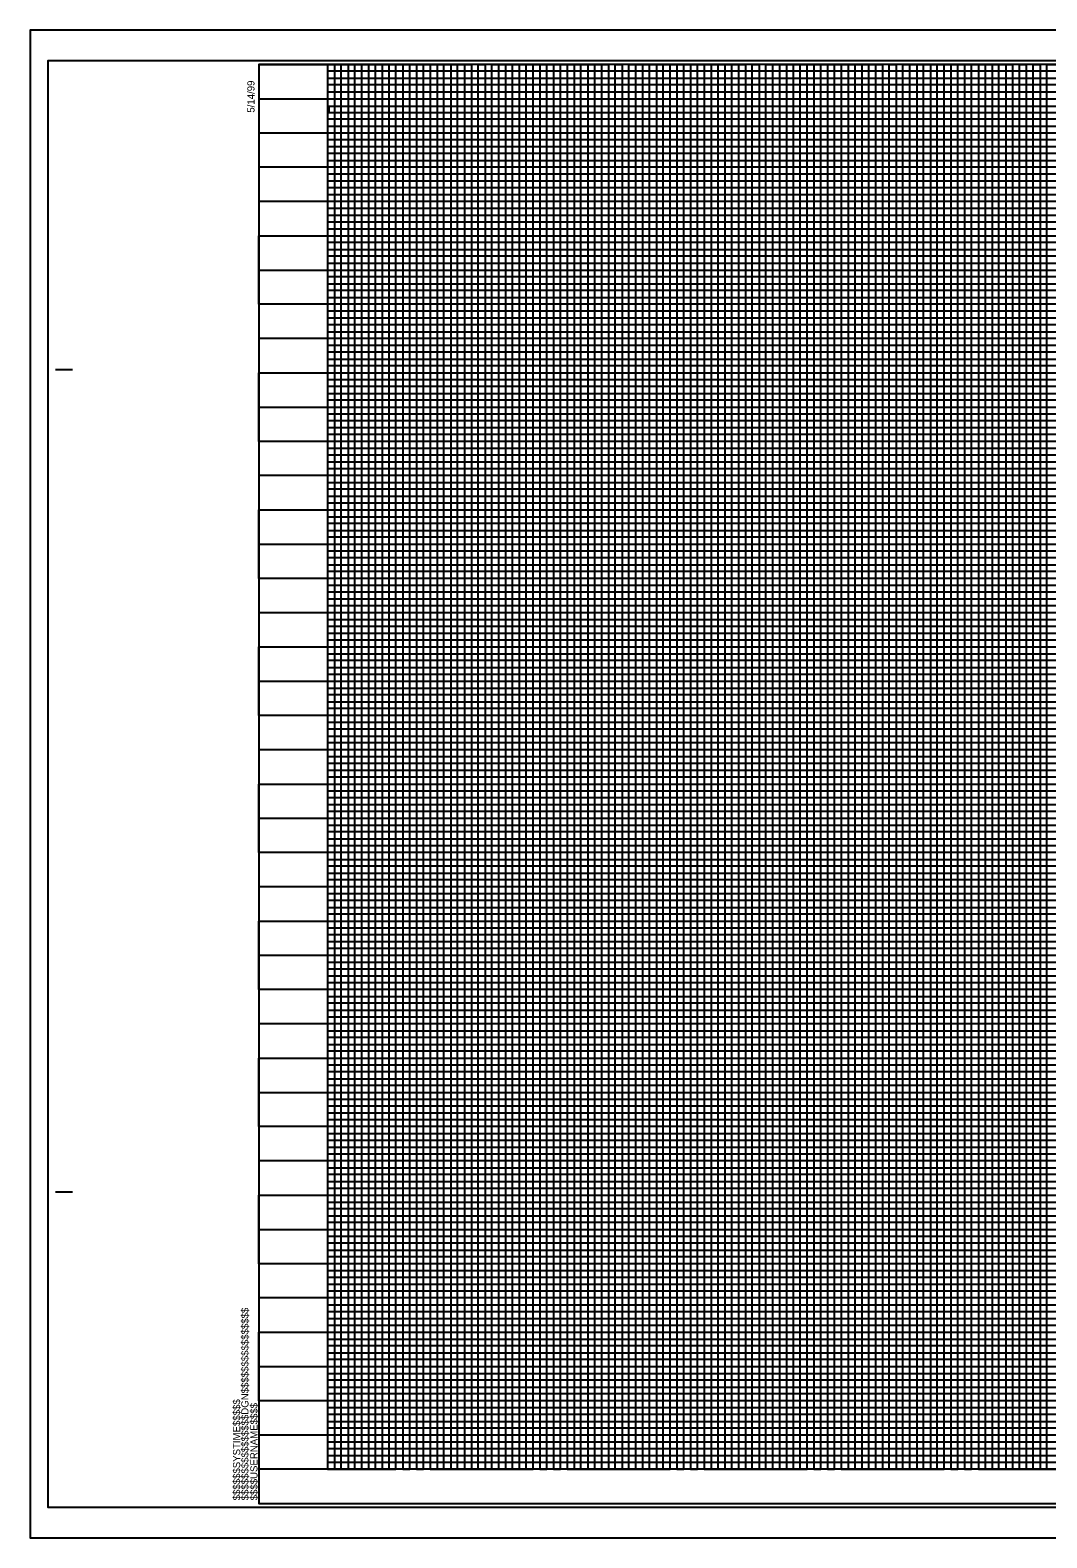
# Model space of a CAD drawing. Extents: x 2345490 to 2436403, y 465165 to 573888.
# Drawn here: x 2381550 to 2382292, y 544859 to 545959 of the extents above; entities that cross this region are included whole.
import ezdxf

# ---------------------------------------------------------------- set-up
doc = ezdxf.new("R2010")
doc.units = 0
for name, color, linetype in [('Old_Level_18', 7, 'Continuous'), ('Old_Level_40', 7, 'Continuous'), ('Old_Level_41', 7, 'Continuous'), ('Old_Level_42', 7, 'Continuous'), ('Old_Level_43', 7, 'Continuous'), ('Old_Level_50', 7, 'Continuous'), ('Old_Level_51', 7, 'Continuous'), ('Old_Level_52', 7, 'Continuous')]:
    doc.layers.add(name, color=color, linetype=linetype)

msp = doc.modelspace()

# ---------------------------------------------------------------- linework, layer by layer
at = {"layer": 'Old_Level_18'}
msp.add_line((2381716.79875, 544884.17225), (2381716.79875, 544884.17225), dxfattribs=at)
msp.add_line((2381716.79875, 544884.17225), (2381716.79875, 544884.17225), dxfattribs=at)
msp.add_lwpolyline([(2383216.79875, 545934.17225), (2381716.79875, 545934.17225), (2381716.79875, 544884.17225), (2383216.79875, 544884.17225)], close=True, dxfattribs=at)
at = {"layer": 'Old_Level_40'}
msp.add_line((2381716.79875, 544884.17225), (2381716.79875, 544884.17225), dxfattribs=at)
msp.add_line((2381716.79875, 544884.17225), (2381716.79875, 544884.17225), dxfattribs=at)
msp.add_line((2381716.79875, 544884.17225), (2381716.79875, 544884.17225), dxfattribs=at)
msp.add_line((2381716.79875, 544884.17225), (2381716.79875, 544884.17225), dxfattribs=at)
at = {"layer": 'Old_Level_41'}
for p, q in [((2381568.29875, 545711.67225), (2381580.79875, 545711.67225)), ((2381568.29875, 545111.67225), (2381580.79875, 545111.67225)), ((2383216.79875, 544909.17225), (2381716.79875, 544909.17225))]:
    msp.add_line(p, q, dxfattribs=at)
for points in [[(2381716.79875, 545934.17225), (2381766.79875, 545934.17225), (2381766.79875, 544909.17225), (2381816.79875, 544909.17225), (2381816.79875, 545934.17225), (2381866.79875, 545934.17225), (2381866.79875, 544909.17225), (2381916.79875, 544909.17225), (2381916.79875, 545934.17225), (2381966.79875, 545934.17225), (2381966.79875, 544909.17225), (2382016.79875, 544909.17225), (2382016.79875, 545934.17225), (2382066.79875, 545934.17225), (2382066.79875, 544909.17225), (2382116.79875, 544909.17225), (2382116.79875, 545934.17225), (2382166.79875, 545934.17225), (2382166.79875, 544909.17225), (2382216.79875, 544909.17225), (2382216.79875, 545934.17225), (2382266.79875, 545934.17225), (2382266.79875, 544909.17225), (2382316.79875, 544909.17225)], [(2381791.79875, 544909.17225), (2381791.79875, 545934.17225), (2381841.79875, 545934.17225), (2381841.79875, 544909.17225), (2381891.79875, 544909.17225), (2381891.79875, 545934.17225), (2381941.79875, 545934.17225), (2381941.79875, 544909.17225), (2381991.79875, 544909.17225), (2381991.79875, 545934.17225), (2382041.79875, 545934.17225), (2382041.79875, 544909.17225), (2382091.79875, 544909.17225), (2382091.79875, 545934.17225), (2382141.79875, 545934.17225), (2382141.79875, 544909.17225), (2382191.79875, 544909.17225), (2382191.79875, 545934.17225), (2382241.79875, 545934.17225), (2382241.79875, 544909.17225), (2382291.79875, 544909.17225), (2382291.79875, 545934.17225), (2382341.79875, 545934.17225)], [(2381716.79875, 545884.17225), (2383016.74875, 545884.17225)], [(2383016.74875, 545834.17225), (2381716.79875, 545834.17225), (2381716.79875, 545784.12225), (2383216.79875, 545784.12225)], [(2383216.79875, 545759.17225), (2381716.79875, 545759.17225), (2381716.79875, 545809.17225), (2383016.74875, 545809.17225)], [(2383216.79875, 545734.17225), (2381716.79875, 545734.17225), (2381716.79875, 545684.17225), (2383216.79875, 545684.17225)], [(2383216.79875, 545659.17225), (2381716.79875, 545659.17225), (2381716.79875, 545709.17225), (2383216.79875, 545709.17225)], [(2383216.79875, 545634.17225), (2381716.79875, 545634.17225), (2381716.79875, 545584.17225), (2383216.79875, 545584.17225)], [(2383216.79875, 545534.17225), (2381716.79875, 545534.17225), (2381716.79875, 545484.17225), (2383216.79875, 545484.17225)], [(2383216.79875, 545434.17225), (2381716.79875, 545434.17225), (2381716.79875, 545384.17225), (2383216.79875, 545384.17225)], [(2383216.79875, 545334.17225), (2381716.79875, 545334.17225), (2381716.79875, 545284.17225), (2383216.79875, 545284.17225)], [(2383216.79875, 545259.17225), (2381716.79875, 545259.17225), (2381716.79875, 545309.17225), (2383216.79875, 545309.17225)], [(2383216.79875, 545234.17225), (2381716.79875, 545234.17225), (2381716.79875, 545184.17225), (2383216.79875, 545184.17225)], [(2383216.79875, 545159.17225), (2381716.79875, 545159.17225), (2381716.79875, 545209.17225), (2383216.79875, 545209.17225)], [(2383216.79875, 545134.17225), (2381716.79875, 545134.17225), (2381716.79875, 545084.17225), (2383216.79875, 545084.17225)], [(2383216.79875, 545034.17225), (2381716.79875, 545034.17225), (2381716.79875, 544984.17225), (2383216.79875, 544984.17225)], [(2383216.79875, 544959.17225), (2381716.79875, 544959.17225), (2381716.79875, 545009.17225), (2383216.79875, 545009.17225)], [(2383216.79875, 544934.17225), (2381716.79875, 544934.17225)], [(2381754.29875, 544884.17225), (2381754.29875, 544884.17225)]]:
    msp.add_lwpolyline(points, dxfattribs=at)
at = {"layer": 'Old_Level_42'}
for points in [[(2383016.74875, 545859.17225), (2381716.89875, 545859.17225), (2381716.89875, 545909.12225), (2383016.74875, 545909.12225)], [(2383216.79875, 545559.17225), (2381716.79875, 545559.17225), (2381716.79875, 545609.17225), (2383216.79875, 545609.17225)], [(2383216.79875, 545459.17225), (2381716.79875, 545459.17225), (2381716.79875, 545509.17225), (2383216.79875, 545509.17225)], [(2383216.79875, 545359.17225), (2381716.79875, 545359.17225), (2381716.79875, 545409.17225), (2383216.79875, 545409.17225)], [(2383216.79875, 545059.17225), (2381716.79875, 545059.17225), (2381716.79875, 545109.17225), (2383216.79875, 545109.17225)]]:
    msp.add_lwpolyline(points, dxfattribs=at)
at = {"layer": 'Old_Level_43'}
for p, q in [((2383166.79875, 545754.17225), (2381766.79875, 545754.17225)), ((2381766.79875, 545754.17225), (2381766.79875, 545749.17225)), ((2381766.79875, 545749.17225), (2383166.79875, 545749.17225)), ((2383166.79875, 545729.17225), (2381766.79875, 545729.17225))]:
    msp.add_line(p, q, dxfattribs=at)
for points in [[(2381771.79875, 545934.17225), (2381776.79875, 545934.17225), (2381781.79875, 545934.17225), (2381786.79875, 545934.17225), (2381796.79875, 545934.17225), (2381763.74875, 545934.17225), (2381768.74875, 545934.17225), (2381726.79875, 545934.17225), (2381731.79875, 545934.17225), (2381736.79875, 545934.17225), (2381746.79875, 545934.17225), (2381751.79875, 545934.17225), (2381756.79875, 545934.17225), (2381761.79875, 545934.17225), (2381771.79875, 545934.17225), (2381771.79875, 544909.17225), (2381776.79875, 544909.17225), (2381776.79875, 545934.17225), (2381781.79875, 545934.17225), (2381781.79875, 544909.17225), (2381786.79875, 544909.17225), (2381786.79875, 545934.17225), (2381796.79875, 545934.17225), (2381796.79875, 544909.17225), (2381801.79875, 544909.17225), (2381801.79875, 545934.17225), (2381806.79875, 545934.17225), (2381806.79875, 544909.17225), (2381811.79875, 544909.17225), (2381811.79875, 545934.17225), (2381821.79875, 545934.17225), (2381821.79875, 544909.17225), (2381826.79875, 544909.17225), (2381826.79875, 545934.17225), (2381831.79875, 545934.17225), (2381831.79875, 544909.17225), (2381836.79875, 544909.17225), (2381836.79875, 545934.17225), (2381846.79875, 545934.17225), (2381846.79875, 544909.17225), (2381851.79875, 544909.17225), (2381851.79875, 545934.17225), (2381856.79875, 545934.17225), (2381856.79875, 544909.17225), (2381861.79875, 544909.17225), (2381861.79875, 545934.17225), (2381871.79875, 545934.17225), (2381871.79875, 544909.17225), (2381876.79875, 544909.17225), (2381876.79875, 545934.17225), (2381881.79875, 545934.17225), (2381881.79875, 544909.17225), (2381886.79875, 544909.17225), (2381886.79875, 545934.17225), (2381896.79875, 545934.17225), (2381896.79875, 544909.17225), (2381901.79875, 544909.17225), (2381901.79875, 545934.17225), (2381906.79875, 545934.17225), (2381906.79875, 544909.17225), (2381911.79875, 544909.17225), (2381911.79875, 545934.17225), (2381921.79875, 545934.17225), (2381921.79875, 544909.17225), (2381926.79875, 544909.17225), (2381926.79875, 545934.17225), (2381931.79875, 545934.17225), (2381931.79875, 544909.17225)], [(2381931.79875, 544909.17225), (2381936.79875, 544909.17225), (2381936.79875, 545934.17225), (2381946.79875, 545934.17225), (2381946.79875, 544909.17225), (2381951.79875, 544909.17225), (2381951.79875, 545934.17225), (2381956.79875, 545934.17225), (2381956.79875, 544909.17225), (2381961.79875, 544909.17225), (2381961.79875, 545934.17225), (2381971.79875, 545934.17225), (2381971.79875, 544909.17225), (2381976.79875, 544909.17225), (2381976.79875, 545934.17225), (2381976.79875, 545934.17225), (2381981.79875, 545934.17225), (2381981.79875, 544909.17225), (2381986.79875, 544909.17225), (2381986.79875, 545934.17225), (2381996.79875, 545934.17225), (2381996.79875, 544909.17225), (2382001.79875, 544909.17225), (2382001.79875, 545934.17225), (2382006.79875, 545934.17225), (2382006.79875, 544909.17225), (2382011.79875, 544909.17225), (2382011.79875, 545934.17225), (2382021.79875, 545934.17225), (2382021.79875, 544909.17225), (2382026.79875, 544909.17225), (2382026.79875, 545934.17225), (2382031.79875, 545934.17225), (2382031.79875, 544909.17225), (2382036.79875, 544909.17225), (2382036.79875, 545934.17225), (2382046.79875, 545934.17225), (2382046.79875, 544909.17225), (2382051.79875, 544909.17225), (2382051.79875, 545934.17225), (2382056.79875, 545934.17225), (2382056.79875, 544909.17225), (2382061.79875, 544909.17225), (2382061.79875, 545934.17225), (2382071.79875, 545934.17225), (2382071.79875, 544909.17225), (2382076.79875, 544909.17225), (2382076.79875, 545934.17225), (2382081.79875, 545934.17225), (2382081.79875, 544909.17225), (2382086.79875, 544909.17225), (2382086.79875, 545934.17225), (2382096.79875, 545934.17225), (2382096.79875, 544909.17225), (2382111.79875, 544909.17225), (2382111.79875, 545934.17225), (2382121.79875, 545934.17225), (2382121.79875, 544909.17225), (2382126.79875, 544909.17225), (2382126.79875, 545934.17225), (2382131.79875, 545934.17225), (2382131.79875, 544909.17225), (2382136.79875, 544909.17225), (2382136.79875, 545934.17225), (2382146.79875, 545934.17225), (2382146.79875, 544909.17225), (2382151.79875, 544909.17225), (2382151.79875, 545934.17225), (2382156.79875, 545934.17225), (2382156.79875, 544909.17225), (2382161.79875, 544909.17225), (2382161.79875, 545934.17225), (2382171.79875, 545934.17225), (2382171.79875, 544909.17225), (2382176.79875, 544909.17225), (2382176.79875, 545934.17225), (2382181.79875, 545934.17225), (2382181.79875, 544909.17225), (2382186.79875, 544909.17225), (2382186.79875, 545934.17225), (2382196.79875, 545934.17225), (2382196.79875, 544909.17225), (2382201.79875, 544909.17225), (2382201.79875, 545934.17225), (2382206.79875, 545934.17225), (2382206.79875, 544909.17225), (2382211.79875, 544909.17225), (2382211.79875, 545934.17225), (2382221.79875, 545934.17225), (2382221.79875, 544909.17225), (2382226.79875, 544909.17225), (2382226.79875, 545934.17225), (2382231.79875, 545934.17225), (2382231.79875, 544909.17225), (2382236.79875, 544909.17225), (2382236.79875, 545934.17225), (2382246.79875, 545934.17225), (2382246.79875, 544909.17225)], [(2382101.79875, 545934.17225), (2382101.79875, 544909.17225), (2382106.79875, 544909.17225), (2382106.79875, 545934.17225)], [(2382101.79875, 545933.57225), (2382101.79875, 544909.17225), (2382106.79875, 544909.17225), (2382106.79875, 545933.57225)], [(2382251.79875, 545934.17225), (2382251.79875, 544909.17225), (2382256.79875, 544909.17225), (2382256.79875, 545934.17225), (2382261.79875, 545934.17225), (2382261.79875, 544909.17225), (2382271.79875, 544909.17225), (2382271.79875, 545934.17225), (2382276.79875, 545934.17225), (2382276.79875, 544909.17225), (2382281.79875, 544909.17225), (2382281.79875, 545934.17225), (2382286.79875, 545934.17225), (2382286.79875, 544909.17225)], [(2383016.74875, 545929.17225), (2381766.79875, 545929.17225), (2381766.79875, 545924.17225), (2383016.74875, 545924.17225)], [(2383016.74875, 545919.17225), (2381766.79875, 545919.17225), (2381766.79875, 545914.17225), (2383016.74875, 545914.17225)], [(2383016.74875, 545903.42225), (2381767.79875, 545903.42225), (2381767.79875, 545899.17225), (2383016.74875, 545899.17225)], [(2383016.74875, 545894.17225), (2381766.79875, 545894.17225), (2381766.79875, 545889.17225), (2383016.74875, 545889.17225)], [(2383016.74875, 545879.17225), (2381766.79875, 545879.17225), (2381766.79875, 545874.17225), (2383016.74875, 545874.17225)], [(2383016.74875, 545869.17225), (2381766.79875, 545869.17225), (2381766.79875, 545864.17225), (2383016.74875, 545864.17225)], [(2383016.74875, 545854.17225), (2381766.79875, 545854.17225), (2381766.79875, 545849.17225), (2383016.74875, 545849.17225)], [(2383016.74875, 545844.17225), (2381766.79875, 545844.17225), (2381766.79875, 545839.17225), (2383016.74875, 545839.17225)], [(2383016.74875, 545829.17225), (2381766.79875, 545829.17225), (2381766.79875, 545824.17225), (2383016.74875, 545824.17225)], [(2383016.74875, 545819.17225), (2381766.79875, 545819.17225), (2381766.79875, 545814.17225), (2383016.74875, 545814.17225)], [(2383016.74875, 545804.17225), (2381766.79875, 545804.17225), (2381766.79875, 545799.17225), (2383016.74875, 545799.17225)], [(2383166.79875, 545794.17225), (2381766.79875, 545794.17225), (2381766.79875, 545794.17225), (2381766.79875, 545774.17225), (2383166.79875, 545774.17225)], [(2381766.79875, 545789.17225), (2383166.79875, 545789.17225)], [(2383166.79875, 545779.17225), (2381766.79875, 545779.17225)], [(2383166.79875, 545769.17225), (2381766.79875, 545769.17225), (2381766.79875, 545764.17225), (2383166.79875, 545764.17225)], [(2383166.79875, 545744.17225), (2381766.79875, 545744.17225), (2381766.79875, 545739.17225), (2383166.79875, 545739.17225)], [(2383166.79875, 545724.17225), (2381766.79875, 545724.17225), (2381766.79875, 545719.17225), (2383166.79875, 545719.17225)], [(2383166.79875, 545714.17225), (2381766.79875, 545714.17225)], [(2381766.79875, 545704.17225), (2383166.79875, 545704.17225)], [(2383166.79875, 545699.17225), (2381766.79875, 545699.17225), (2381766.79875, 545694.17225), (2383166.79875, 545694.17225)], [(2383166.79875, 545689.17225), (2381766.79875, 545689.17225), (2381766.79875, 545679.17225), (2383166.79875, 545679.17225)], [(2383166.79875, 545674.17225), (2381766.79875, 545674.17225), (2381766.79875, 545669.17225), (2383166.79875, 545669.17225)], [(2383166.79875, 545664.17225), (2381766.79875, 545664.17225), (2381766.79875, 545654.17225), (2383166.79875, 545654.17225)], [(2383166.79875, 545649.17225), (2381766.79875, 545649.17225), (2381766.79875, 545644.17225), (2383166.79875, 545644.17225)], [(2383166.79875, 545639.17225), (2381766.79875, 545639.17225), (2381766.79875, 545629.17225), (2383166.79875, 545629.17225)], [(2383166.79875, 545624.17225), (2381766.79875, 545624.17225), (2381766.79875, 545619.17225), (2383166.79875, 545619.17225)], [(2383166.79875, 545614.17225), (2381766.79875, 545614.17225), (2381766.79875, 545604.17225), (2383166.79875, 545604.17225)], [(2383166.79875, 545599.17225), (2381766.79875, 545599.17225), (2381766.79875, 545594.17225), (2383166.79875, 545594.17225)], [(2383166.79875, 545589.17225), (2381766.79875, 545589.17225), (2381766.79875, 545579.17225), (2383166.79875, 545579.17225)], [(2383166.79875, 545574.17225), (2381766.79875, 545574.17225), (2381766.79875, 545569.17225), (2383166.79875, 545569.17225)], [(2383166.79875, 545564.17225), (2381766.79875, 545564.17225), (2381766.79875, 545554.17225), (2383166.79875, 545554.17225)], [(2383166.79875, 545549.17225), (2381766.79875, 545549.17225), (2381766.79875, 545544.17225), (2383166.79875, 545544.17225)], [(2383166.79875, 545539.17225), (2381766.79875, 545539.17225), (2381766.79875, 545529.17225), (2383166.79875, 545529.17225)], [(2383166.79875, 545524.17225), (2381766.79875, 545524.17225), (2381766.79875, 545519.17225), (2383166.79875, 545519.17225)], [(2383166.79875, 545514.17225), (2381766.79875, 545514.17225), (2381766.79875, 545504.17225), (2383166.79875, 545504.17225)], [(2383166.79875, 545499.17225), (2381766.79875, 545499.17225), (2381766.79875, 545494.17225), (2383166.79875, 545494.17225)], [(2383166.79875, 545489.17225), (2381766.79875, 545489.17225), (2381766.79875, 545479.17225), (2383166.79875, 545479.17225)], [(2383166.79875, 545474.17225), (2381766.79875, 545474.17225), (2381766.79875, 545469.17225), (2383166.79875, 545469.17225)], [(2383166.79875, 545464.17225), (2381766.79875, 545464.17225), (2381766.79875, 545454.17225), (2383166.79875, 545454.17225)], [(2383166.79875, 545449.17225), (2381766.79875, 545449.17225), (2381766.79875, 545444.17225), (2383166.79875, 545444.17225)], [(2383166.79875, 545439.17225), (2381766.79875, 545439.17225), (2381766.79875, 545429.17225), (2383166.79875, 545429.17225)], [(2383166.79875, 545424.17225), (2381766.79875, 545424.17225), (2381766.79875, 545419.17225), (2383166.79875, 545419.17225)], [(2383166.79875, 545414.17225), (2381766.79875, 545414.17225)], [(2381766.79875, 545404.17225), (2383166.79875, 545404.17225)], [(2383166.79875, 545399.17225), (2381766.79875, 545399.17225), (2381766.79875, 545394.17225), (2383166.79875, 545394.17225)], [(2383166.79875, 545389.17225), (2381766.79875, 545389.17225), (2381766.79875, 545379.17225), (2383166.79875, 545379.17225)], [(2383166.79875, 545374.17225), (2381766.79875, 545374.17225), (2381766.79875, 545369.17225), (2383166.79875, 545369.17225)], [(2383166.79875, 545364.17225), (2381766.79875, 545364.17225), (2381766.79875, 545354.17225), (2383166.79875, 545354.17225)], [(2383166.79875, 545349.17225), (2381766.79875, 545349.17225), (2381766.79875, 545344.17225), (2383166.79875, 545344.17225)], [(2383166.79875, 545339.17225), (2381766.79875, 545339.17225), (2381766.79875, 545329.17225), (2383166.79875, 545329.17225)], [(2383166.79875, 545324.17225), (2381766.79875, 545324.17225), (2381766.79875, 545319.17225), (2383166.79875, 545319.17225)], [(2383166.79875, 545314.17225), (2381766.79875, 545314.17225), (2381766.79875, 545304.17225), (2383166.79875, 545304.17225)], [(2383166.79875, 545299.17225), (2381766.79875, 545299.17225), (2381766.79875, 545294.17225), (2383166.79875, 545294.17225)], [(2383166.79875, 545289.17225), (2381766.79875, 545289.17225), (2381766.79875, 545279.17225), (2383166.79875, 545279.17225)], [(2383166.79875, 545274.17225), (2381766.79875, 545274.17225), (2381766.79875, 545269.17225), (2383166.79875, 545269.17225)], [(2383166.79875, 545264.17225), (2381766.79875, 545264.17225), (2381766.79875, 545254.17225), (2383166.79875, 545254.17225)], [(2383166.79875, 545249.17225), (2381766.79875, 545249.17225), (2381766.79875, 545244.17225), (2383166.79875, 545244.17225)], [(2383166.79875, 545239.17225), (2381766.79875, 545239.17225), (2381766.79875, 545229.17225), (2383166.79875, 545229.17225)], [(2383166.79875, 545224.17225), (2381766.79875, 545224.17225), (2381766.79875, 545219.17225), (2383166.79875, 545219.17225)], [(2383166.79875, 545214.17225), (2381766.79875, 545214.17225), (2381766.79875, 545204.17225), (2383166.79875, 545204.17225)], [(2383166.79875, 545199.17225), (2381766.79875, 545199.17225), (2381766.79875, 545194.17225), (2383166.79875, 545194.17225)], [(2383166.79875, 545189.17225), (2381766.79875, 545189.17225), (2381766.79875, 545179.17225), (2383166.79875, 545179.17225)], [(2383166.79875, 545174.17225), (2381766.79875, 545174.17225), (2381766.79875, 545169.17225), (2383166.79875, 545169.17225)], [(2383166.79875, 545164.17225), (2381766.79875, 545164.17225), (2381766.79875, 545154.17225), (2383166.79875, 545154.17225)], [(2383166.79875, 545149.17225), (2381766.79875, 545149.17225), (2381766.79875, 545144.17225), (2383166.79875, 545144.17225)], [(2383166.79875, 545139.17225), (2381766.79875, 545139.17225), (2381766.79875, 545129.17225), (2383166.79875, 545129.17225)], [(2383166.79875, 545124.17225), (2381766.79875, 545124.17225), (2381766.79875, 545119.17225), (2383166.79875, 545119.17225)], [(2383166.79875, 545114.17225), (2381766.79875, 545114.17225)], [(2381766.79875, 545104.17225), (2383166.79875, 545104.17225)], [(2383166.79875, 545099.17225), (2381766.79875, 545099.17225), (2381766.79875, 545094.17225), (2383166.79875, 545094.17225)], [(2383166.79875, 545089.17225), (2381766.79875, 545089.17225)], [(2381766.79875, 545079.17225), (2383166.79875, 545079.17225)], [(2383166.79875, 545074.17225), (2381766.79875, 545074.17225), (2381766.79875, 545069.17225), (2383166.79875, 545069.17225)], [(2383166.79875, 545064.17225), (2381766.79875, 545064.17225), (2381766.79875, 545054.17225), (2383166.79875, 545054.17225)], [(2383166.79875, 545049.17225), (2381766.79875, 545049.17225), (2381766.79875, 545044.17225), (2383166.79875, 545044.17225)], [(2383166.79875, 545039.17225), (2381766.79875, 545039.17225), (2381766.79875, 545029.17225), (2383166.79875, 545029.17225)], [(2383166.79875, 545024.17225), (2381766.79875, 545024.17225), (2381766.79875, 545019.17225), (2383166.79875, 545019.17225)], [(2383166.79875, 545014.17225), (2381766.79875, 545014.17225), (2381766.79875, 545004.17225), (2383166.79875, 545004.17225)], [(2383166.79875, 544999.17225), (2381766.79875, 544999.17225), (2381766.79875, 544994.17225), (2383166.79875, 544994.17225)], [(2383166.79875, 544989.17225), (2381766.79875, 544989.17225), (2381766.79875, 544979.17225), (2383166.79875, 544979.17225)], [(2383166.79875, 544974.17225), (2381766.79875, 544974.17225), (2381766.79875, 544969.17225), (2383166.79875, 544969.17225)], [(2383166.79875, 544964.17225), (2381766.79875, 544964.17225), (2381766.79875, 544954.17225), (2383166.79875, 544954.17225)], [(2383166.79875, 544949.17225), (2381766.79875, 544949.17225), (2381766.79875, 544944.17225), (2383166.79875, 544944.17225)], [(2383166.79875, 544939.17225), (2381766.79875, 544939.17225), (2381766.79875, 544929.17225), (2383166.79875, 544929.17225)], [(2383166.79875, 544924.17225), (2381766.79875, 544924.17225), (2381766.79875, 544919.17225), (2383166.79875, 544919.17225)], [(2383166.79875, 544914.17225), (2381766.79875, 544914.17225)]]:
    msp.add_lwpolyline(points, dxfattribs=at)
at = {"layer": 'Old_Level_50'}
msp.add_line((2381549.79875, 544859.17225), (2381549.79875, 544859.17225), dxfattribs=at)
msp.add_lwpolyline([(2383229.29875, 545936.72225), (2381562.79875, 545936.72225), (2381562.79875, 544881.62225), (2383229.29875, 544881.62225)], close=True, dxfattribs=at)
at = {"layer": 'Old_Level_51'}
msp.add_lwpolyline([(2383233.79875, 545959.17225), (2381549.79875, 545959.17225), (2381549.79875, 544859.17225), (2383233.79875, 544859.17225)], close=True, dxfattribs=at)
at = {"layer": 'Old_Level_52'}
msp.add_line((2381562.79875, 544881.62225), (2381562.79875, 544881.62225), dxfattribs=at)

# ---------------------------------------------------------------- texts
at = {"layer": 'Old_Level_41'}
for s, p in [('5/14/99', (2381713.54875, 545898.97225)), ('$$$$$$$$$$$$$$$$DGN$$$$$$$$$$$$$$$$', (2381709.14875, 544886.53475)), ('$$$$$$SYSTIME$$$$$', (2381703.09875, 544886.53475)), ('$$$$USERNAME$$$$', (2381715.72375, 544886.54725))]:
    msp.add_text(s, height=5.25, rotation=90, dxfattribs=at).set_placement(p)

doc.saveas('drawing.dxf')
